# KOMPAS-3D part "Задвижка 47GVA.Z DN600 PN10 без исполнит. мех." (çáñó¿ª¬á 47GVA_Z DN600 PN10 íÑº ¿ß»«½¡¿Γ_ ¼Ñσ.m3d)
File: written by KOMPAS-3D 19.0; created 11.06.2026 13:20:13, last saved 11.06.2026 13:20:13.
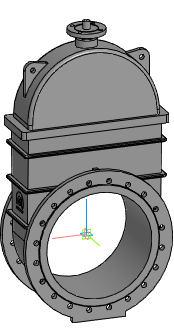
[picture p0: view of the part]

Document properties: Автор: Евгений; Полное имя файла: Z:\3.Личные\kachalov\001_3d для проектировщиков\2.2 Тип 47GVA, 47GVA.Z\_stp\_stp_Задвижка 47GVA.Z DN350-DN1200 без исп.мех\Задвижка 47GVA_Z DN600 PN10 без исполнит_ мех.m3d

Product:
- Part/product: Задвижка 47GVA.Z DN600 PN10 без исполнит. мех.

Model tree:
1. Операция без истории:1  (labels: Задвижка 47GVA.Z DN600 PN10 без исполнит. мех.)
